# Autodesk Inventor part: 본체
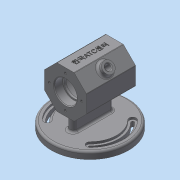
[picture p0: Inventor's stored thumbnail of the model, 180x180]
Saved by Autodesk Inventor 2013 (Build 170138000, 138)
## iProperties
Created: 2017-06
Part Number: 본체
Material: 일반
Document SubType Name: Modeling
Designer: Administrator
Density: 1 g/cm^3
Author: Administrator
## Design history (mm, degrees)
sketch "스케치1"
  geometry: C1 r 55 at (0, 0); 1 further point
  constraints: 1 centre point, 1 coincident
  dimensions: "d0" = 110 diameter of C1
extrude "돌출1" new body sketch "스케치1" distance "d2" = 10; taper "d3" = 0 deg
sketch "스케치2"
  geometry: L1 (55, 10)-(-55, 10) reference; L2 (-55, 0)-(55, 0) reference; L3 (0, 0)-(0, 62); L4 (55, 0)-(55, 92); L5 (55, 92)-(-118.048, 92); L6 (12.426, 92)-(30, 74.426); L7 (30, 74.426)-(30, 49.574); L8 (30, 49.574)-(12.426, 32); L9 (12.426, 32)-(-12.426, 32); L10 (-12.426, 32)-(-30, 49.574); L11 (-30, 49.574)-(-30, 74.426); L12 (-30, 74.426)-(-12.426, 92); L13 (-12.426, 92)-(12.426, 92); C1 r 30 at (0, 62)
  constraints: 22 end point, 2 horizontal alignment, 1 centre point, 1 coincident, 1 parallel, 1 perpendicular, 1 vertical
  dimensions: "d5" = 60 diameter of C1; "d6" = 92 distance of L2.end L4.end; "d9" = 62 distance from line of L2 L3.end
extrude "돌출2" join sketch "스케치2" stored distance "d11" = 70; taper "d12" = 0 deg
sketch "스케치3"
  geometry: L1 (-12.426, 92)-(-30, 74.426) reference; L2 (-30, 74.426)-(-30, 49.574) reference; L3 (-30, 49.574)-(-12.426, 32) reference; L4 (-12.426, 32)-(12.426, 32) reference; L5 (12.426, 32)-(30, 49.574) reference; L6 (30, 49.574)-(30, 74.426) reference; L7 (30, 74.426)-(12.426, 92) reference; L8 (12.426, 92)-(-12.426, 92) reference; L9 (0, 0)-(0, 62); C1 r 14 at (0, 62)
  constraints: 2 end point, 1 centre point, 1 coincident, 1 perpendicular
  dimensions: "d13" = 62 distance of L9.start L9.end; "d14" = 28 diameter of C1
extrude "돌출3" cut sketch "스케치3" stored distance "d15" = 70; taper "d16" = 0 deg
sketch "스케치4"
  geometry: C1 r 14 at (0, 62) reference; C2 r 16 at (0, 62); 1 further point
  constraints: 1 centre point, 1 coincident
  dimensions: "d17" = 32 diameter of C2
extrude "돌출4" cut sketch "스케치4" distance "d19" = 12; taper "d20" = 0 deg
sketch "스케치5"
  geometry: C1 r 14 at (0, -62) reference; C2 r 16 at (0, -62); 1 further point
  constraints: 1 centre point, 1 coincident
  dimensions: "d21" = 32 diameter of C2
extrude "돌출5" cut sketch "스케치5" distance "d23" = 12; taper "d24" = 0 deg
node "작업 평면1"
sketch "스케치6"
  geometry: L1 (-30, 74.426)-(-12.426, 92) reference; L2 (-12.426, 92)-(12.426, 92) reference; L3 (12.426, 92)-(30, 74.426) reference; L4 (30, 74.426)-(30, 49.574) reference; L5 (30, 49.574)-(12.426, 32) reference; L6 (12.426, 32)-(-12.426, 32) reference; L7 (-12.426, 32)-(-30, 49.574) reference; L8 (-30, 49.574)-(-30, 74.426) reference; C1 r 16 at (0, 62) reference; C2 r 25 at (0, 62); 1 further point
  constraints: 1 centre point, 1 coincident
  dimensions: "d25" = 50 diameter of C2
extrude "돌출6" cut sketch "스케치6" stored distance "d27" = 40; taper "d28" = 0 deg
fillet "모깎기1" dims "d29" = 3
chamfer "모따기1" distance "d30" = 1; stored, may be unused: second distance "d31" = 2, angle "d32" = 45 deg
sketch "스케치7"
  geometry: L1 (0, 0)-(-78.073, 0); L2 (0, 0)-(-61.063, 61.063); L3 (0, 0)-(-59.918, -59.918); L4 (0, 0)-(76.949, 76.949); L5 (0, 0)-(92.167, 0); L6 (0, 0)-(54.196, -54.196); C1 r 55 at (0, 0) reference; A1 r 5 centre (-30.406, -30.406) between (-26.87, -26.87) and (-26.67, -33.73); A2 r 5 centre (-30.406, 30.406) between (-26.87, 26.87) and (-26.67, 33.73); A3 r 5 centre (30.406, 30.406) between (26.87, 26.87) and (26.67, 33.73); A4 r 5 centre (30.406, -30.406) between (26.87, -26.87) and (26.67, -33.73); A5 r 38 centre (0, 0) between (-26.87, 26.87) and (-26.87, -26.87); A6 r 38 centre (0, 0) between (26.87, -26.87) and (26.87, 26.87); A7 r 43 centre (0, 0) between (-26.67, 33.73) and (-26.67, -33.73); A8 r 43 centre (0, 0) between (26.67, -33.73) and (26.67, 33.73); A9 r 48 centre (0, 0) between (-33.941, 33.941) and (-33.941, -33.941); A10 r 48 centre (0, 0) between (33.941, -33.941) and (33.941, 33.941)
  constraints: 28 point on circle, 12 end point, 10 centre point, 4 point on line, 3 equal radius, 1 coincident, 1 collinear, 1 horizontal
  dimensions: "d45" = 45 deg angle of L2 L1; "d46" = 45 deg angle of L3 L1; "d47" = 45 deg angle of L4 L5; "d48" = 45 deg angle of L6 L5; "d49" = 10 diameter of A2
extrude "돌출7" cut sketch "스케치7" distance "d51" = 3; taper "d52" = 0 deg
sketch "스케치8"
  geometry: A1 r 5 centre (-30.406, 30.406) between (-26.87, 26.87) and (-33.941, 33.941) reference; A2 r 5 centre (-30.406, -30.406) between (-33.941, -33.941) and (-26.87, -26.87) reference; A3 r 5 centre (30.406, -30.406) between (26.87, -26.87) and (33.941, -33.941) reference; A4 r 48 centre (0, 0) between (33.941, -33.941) and (33.941, 33.941) reference; A5 r 5 centre (30.406, 30.406) between (33.941, 33.941) and (26.87, 26.87) reference; A6 r 38 centre (0, 0) between (26.87, -26.87) and (26.87, 26.87) reference; A7 r 2 centre (-30.406, 30.406) between (-28.991, 28.991) and (-31.82, 31.82); A8 r 2 centre (-30.406, -30.406) between (-31.82, -31.82) and (-28.991, -28.991); A9 r 2 centre (30.406, -30.406) between (28.991, -28.991) and (31.82, -31.82); A10 r 2 centre (30.406, 30.406) between (31.82, 31.82) and (28.991, 28.991); A11 r 41 centre (0, 0) between (-28.991, 28.991) and (-28.991, -28.991); A12 r 41 centre (0, 0) between (28.991, -28.991) and (28.991, 28.991); A13 r 45 centre (0, 0) between (-31.82, 31.82) and (-31.82, -31.82); A14 r 45 centre (0, 0) between (31.82, -31.82) and (31.82, 31.82)
  constraints: 16 point on circle, 8 centre point, 6 coincident, 4 tangent, 3 equal radius
  dimensions: "d53" = 4 diameter of A7
extrude "돌출8" cut sketch "스케치8" stored distance "d55" = 3; taper "d56" = 0 deg
sketch "스케치9" dims "d57" = 46
  geometry: L1 (12.426, 92)-(-12.426, 92) reference; L2 (0, 62)-(0, 85); C1 r 17 at (0, 62) reference; 2 further points
  constraints: 2 coincident, 2 end point, 1 perpendicular, 1 vertical alignment, 2 other
hole "구멍1" sketch "스케치9" at (0, 85) diameter "d59" = 3.242; stored, may be unused: countersink angle "d63" = 90 deg, drill point angle "d65" = 118 deg; dims "d60" = 8, "d61" = 4, "d62" = 2, "d64" = 10
sketch "스케치10" dims "d69" = 46
  geometry: L1 (-30, -49.574)-(-30, -74.426) reference; L2 (0, -62)-(0, -85); C1 r 17 at (0, -62) reference; 2 further points
  constraints: 2 coincident, 2 end point, 1 parallel, 1 vertical alignment, 2 other
hole "구멍2" sketch "스케치10" at (0, -85) diameter "d71" = 3.242; stored, may be unused: countersink angle "d75" = 90 deg, drill point angle "d77" = 118 deg; dims "d72" = 8, "d73" = 4, "d74" = 2, "d76" = 10
fillet "모깎기2" dims "d81" = 0.3
fillet "모깎기3" dims "d82" = 1
fillet "모깎기4" dims "d83" = 1
sketch "스케치11"
  geometry: L1 (0, 0)-(-24.024, 0) reference; C1 r 8 at (-12.012, 35); 2 further points
  constraints: 1 centre point, 1 midpoint, 1 vertical alignment
  dimensions: "d84" = 35 distance from line of L1 C1.centre; "d85" = 16 diameter of C1
extrude "돌출9" join sketch "스케치11" distance "d86" = 7; taper "d87" = 0 deg
fillet "모깎기5" dims "d88" = 3
sketch "스케치12"
  geometry: C1 r 8 at (0, 0) reference; C2 r 4 at (0, 0); 1 further point
  constraints: 1 centre point, 1 coincident
  dimensions: "d89" = 8 diameter of C2
extrude "돌출10" cut sketch "스케치12" distance "d91" = 27.5; taper "d92" = 0 deg
chamfer "모따기2" distance "d93" = 1; stored, may be unused: second distance "d94" = 2, angle "d95" = 45 deg
sketch "스케치13"
  geometry: L1 (24.024, 0)-(0, 0) reference; L2 (9.902, 9.666)-(9.902, 60.334); L3 (9.902, 60.334)-(14.708, 60.334); L4 (14.708, 60.334)-(14.708, 9.666); L5 (14.708, 9.666)-(9.902, 9.666); L6 (12.305, 9.666)-(12.305, 60.334); L7 (14.708, 35)-(9.902, 35); L8 (-17.695, 0)-(-17.695, 70) reference; 1 further point
  constraints: 4 end point, 4 midpoint, 2 other
  dimensions: "d96" = 35 distance between parallel lines of L7 L1; "d97" = 30 distance between parallel lines of L6 L8
feature "엠보싱1" sketch "스케치13" dims "d3" = 0, "d98" = 0.5, "d99" = 0
fillet "모깎기6" dims "d100" = 3
sketch "스케치14"
  geometry: L1 (0, 0)-(0, 24); L2 (0, 0)-(0, -24); L3 (-5, 24)-(-5, -24); L4 (5, 24)-(5, -24); C1 r 52 at (0, 0) reference; A1 r 5 centre (0, 24) between (5, 24) and (-5, 24); A2 r 5 centre (0, -24) between (-5, -24) and (5, -24)
  constraints: 8 end point, 4 point on circle, 3 tangent, 2 centre point, 2 coincident, 2 collinear, 1 equal radius, 1 parallel, 1 vertical
  dimensions: "d101" = 48 distance of L2.end L1.end; "d103" = 10 diameter of A1
extrude "돌출11" join sketch "스케치14" stored distance "d104" = 27.5; taper "d105" = 0 deg
fillet "모깎기7" dims "d106" = 3
node "솔리드1"
pattern_circular "원형 패턴1" dims angle "d67" = 360 deg
pattern_circular "원형 패턴2" dims angle "d79" = 360 deg
node "투영된 루프1"
node "투영된 루프2"
node "투영된 루프3"
node "투영된 루프4"
other parameters: "d33" = 96, "d35" = 76, "d38" = 86, "d41" = 96, "d43" = 76, "d44" = 86
